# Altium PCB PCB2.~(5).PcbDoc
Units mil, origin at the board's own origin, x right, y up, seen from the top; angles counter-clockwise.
Board outline 6000 x 4000 mil, 2 copper layers (Top Layer, Bottom Layer); 4 components, 3 nets, 8 pads, 0 vias.
Unrouted connection lines stored in the file: 5.
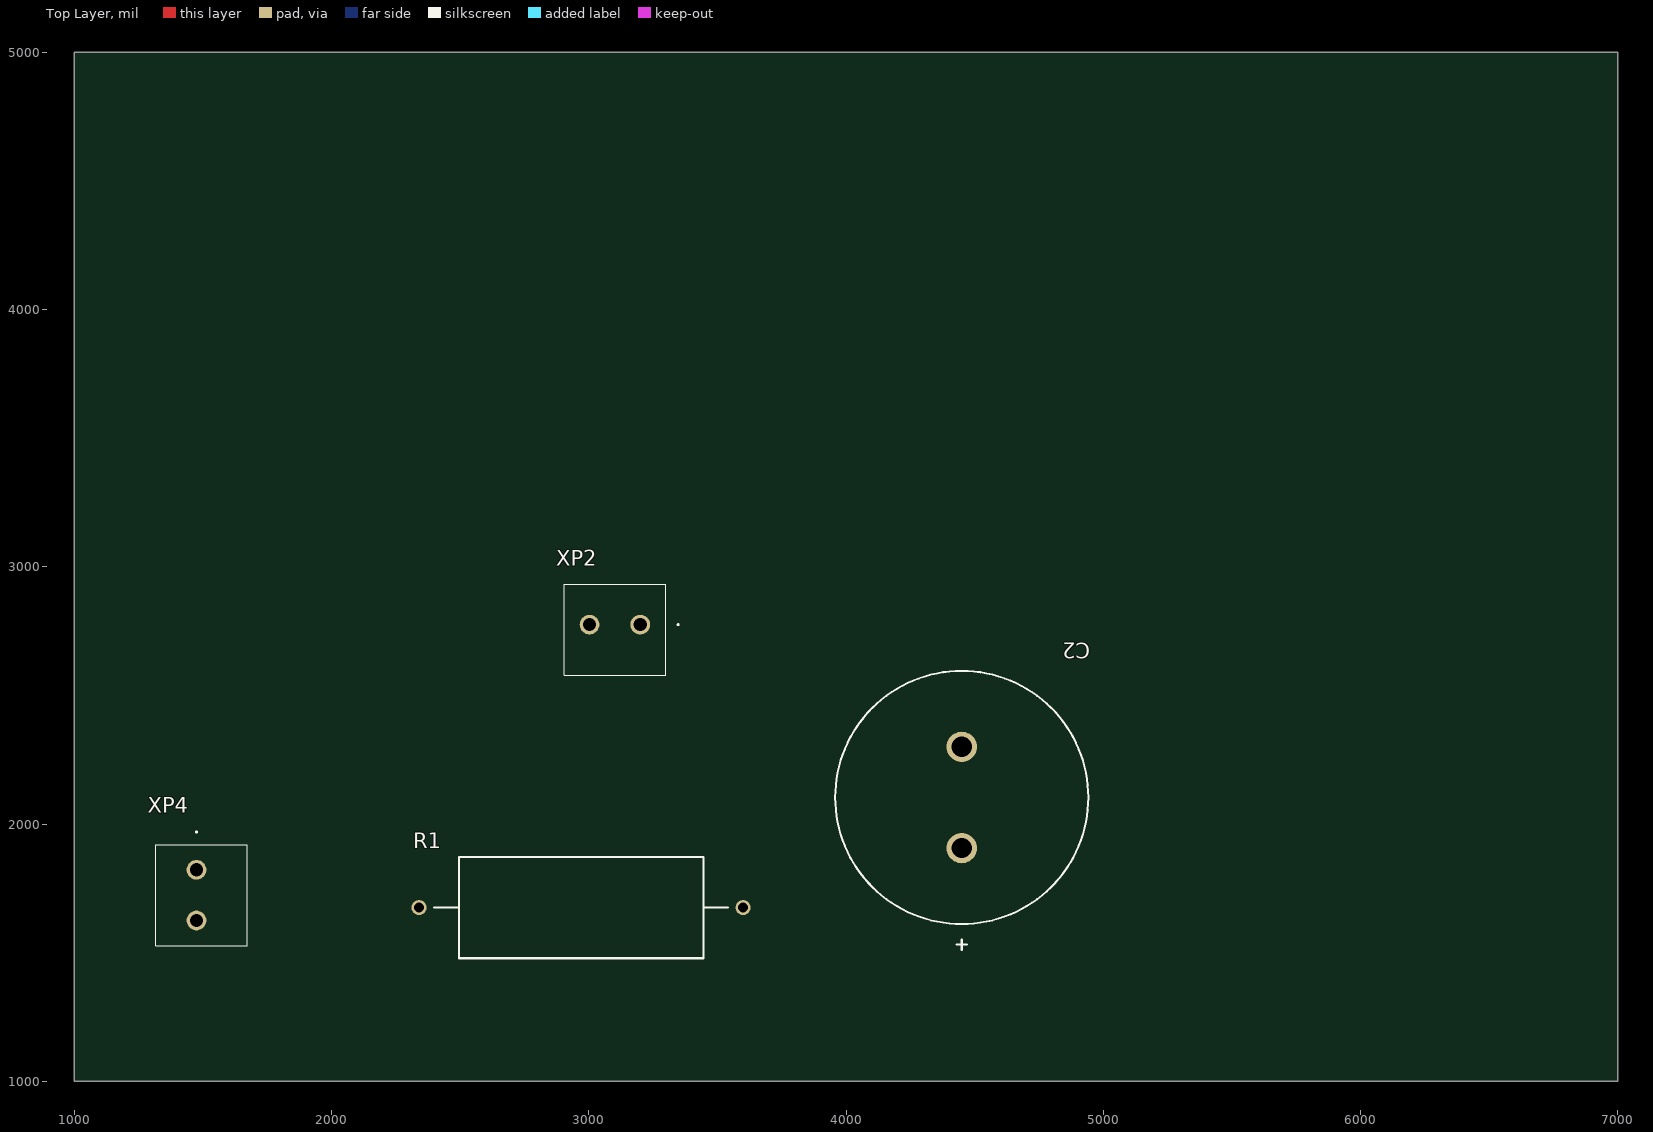
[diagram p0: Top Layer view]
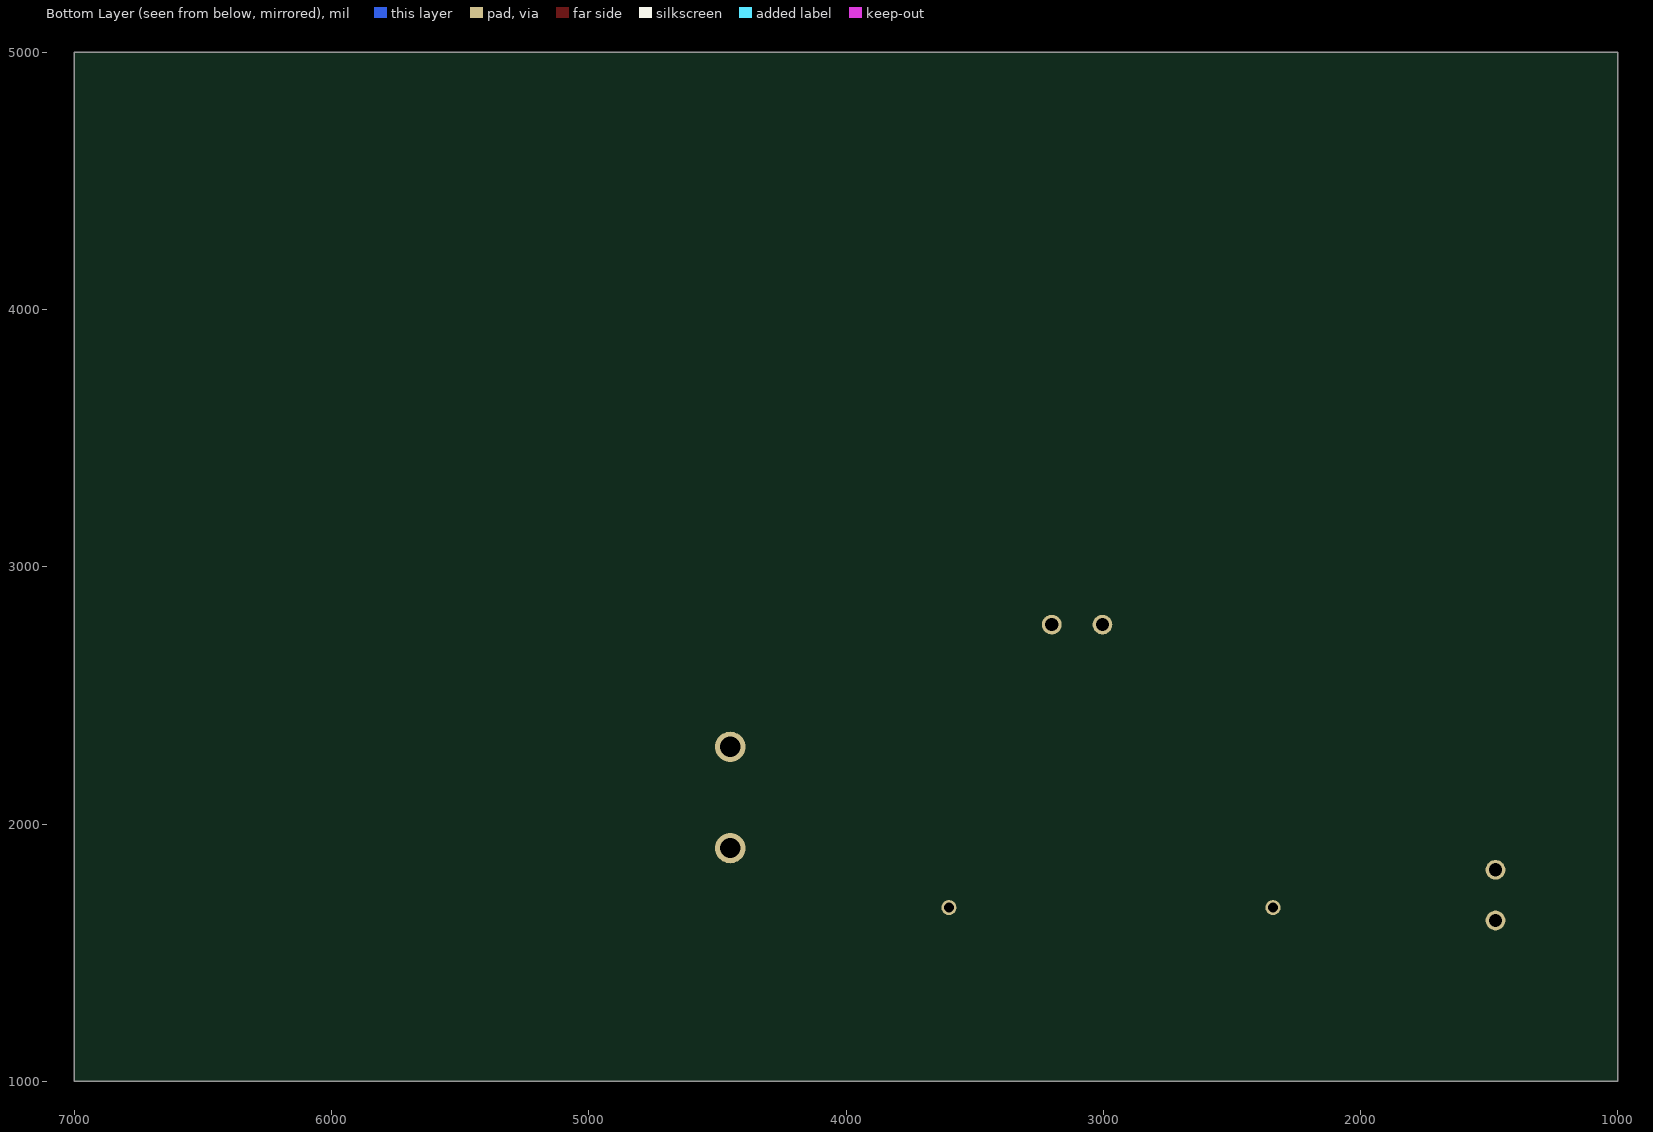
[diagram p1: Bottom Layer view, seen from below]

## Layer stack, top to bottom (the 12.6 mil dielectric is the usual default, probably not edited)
Top Solder: solder mask 0.4, Solder Resist, Dk 3.5
Top Layer: signal copper 1.4
Dielectric 1: dielectric 12.6, FR-4, Dk 4.8
Bottom Layer: signal copper 1.4
Bottom Solder: solder mask 0.4, Solder Resist, Dk 3.5

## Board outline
1000,1000 7000,1000 7000,5000 1000,5000

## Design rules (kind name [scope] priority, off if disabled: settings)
Clearance [All] p1: gap=10 ignorepadtopadclearanceinfootprint=FALSE except(0: Arc-Hole Track-Hole SMDPad-Hole THPad-Hole Via-Hole Fill-Hole Poly-Hole Region-Hole Text-Hole)
PolygonConnect [All] p1: connectstyle=Relief reliefconductorwidth=10 reliefentries=4 polygonreliefangle="90 Angle" airgapwidth=10
RoutingVias [All] p1: holewidth=28 width=50 viastyle="Through Hole" minholewidth=28 minwidth=50 maxholewidth=28 maxwidth=50
SolderMaskExpansion [All] p1: expansion=4 istentingtop=FALSE
Width [All] p1: maxlimit=10 minlimit=10 preferedwidth=10
30 further rules are at their usual default settings.

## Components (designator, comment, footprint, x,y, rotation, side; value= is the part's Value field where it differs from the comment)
C2 "1500uF" K50-98-63V-1500uF 4450,2300 r270 top
R1 "2 Ом" "SQP 5W2" 3600,1675 r180 top
XP2 "DG300-5.0-02P-12-00A_H_" DG3005002P1200AH 3200,2775 r180 top
XP4 "DG300-5.0-02P-12-00A_H_" DG3005002P1200AH 1475,1821.85 r270 top

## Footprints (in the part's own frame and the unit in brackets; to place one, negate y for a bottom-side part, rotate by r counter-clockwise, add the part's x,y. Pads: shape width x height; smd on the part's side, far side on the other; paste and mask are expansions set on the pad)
DG3005002P1200AH [mm]
  round 1.95 hole 1.3: 1(0,0) 2(5,0)
  silkscreen extent -3.8,-4 7.5,5, body extent -2.46,-4 7.54,5, height 12.6
K50-98-63V-1500uF [mm]
  round 3 hole 2: 1(0,0) 2(10,0)
  silkscreen extent -7.5,-12.5 20.05,12.5, body extent -7.5,-12.5 17.5,12.5, height 30
"SQP 5W2" [mm]
  round 1.5 hole 1: 1(0,0) 2(32,0)
  silkscreen extent 1.5,-5 30.5,5, body extent -0.35,-5 32.35,5, height 9

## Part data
C2: library part K50-98-63V-1500uF
R1: library part "SQP 5W"
XP2 XP4: "Клеммник винтовой, 2-контактный, 5мм, прямой", Manufacturer_Name=Degson, Manufacturer_Part_Number=DG300-5.0-02P-12-00A(H)

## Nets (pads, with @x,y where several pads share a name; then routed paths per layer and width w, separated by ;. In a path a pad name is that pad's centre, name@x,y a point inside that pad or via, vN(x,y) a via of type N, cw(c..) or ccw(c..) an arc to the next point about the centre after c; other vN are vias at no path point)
GND: C2.1 XP2.1 XP4.1
NetR1_2: R1.2 XP4.2
VCC1: C2.2 R1.1 XP2.2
